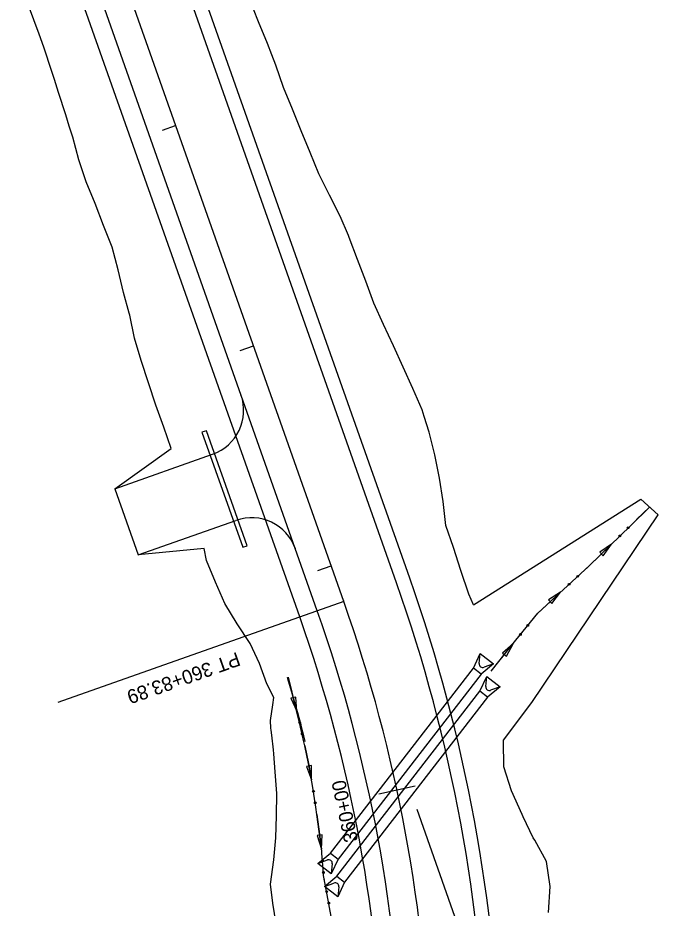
# Model space of a CAD drawing. Extents: x 948761 to 996004, y 1858548 to 1925175.
# Drawn here: x 961167 to 961441.5, y 1906970.6 to 1907351.9 of the extents above; entities that cross this region are included whole.
import ezdxf

# ---------------------------------------------------------------- set-up
doc = ezdxf.new("R2010")
doc.units = 0
for name, color, linetype in [('62', 7, 'Continuous'), ('DRAINAGE STRUCTURES', 7, 'Continuous'), ('R_Drainage', 7, 'Continuous'), ('R_Horz Alg', 7, 'Continuous'), ('R_Horz Alg Annot', 7, 'Continuous'), ('R_Proposed Const Limits', 7, 'Continuous'), ('R_Proposed Road', 7, 'Continuous')]:
    doc.layers.add(name, color=color, linetype=linetype)

msp = doc.modelspace()

# ---------------------------------------------------------------- linework, layer by layer
at = {"layer": '62'}
for p, q in [((961421.48, 1907126.54), (961416.45, 1907123.1)), ((961417.93, 1907121.59), (961421.48, 1907126.54)), ((961416.45, 1907123.1), (961417.93, 1907121.59)), ((961399.62, 1907105.94), (961394.48, 1907102.67)), ((961395.91, 1907101.11), (961399.62, 1907105.94)), ((961394.48, 1907102.67), (961395.91, 1907101.11)), ((961379.34, 1907083.9), (961374.76, 1907079.88)), ((961376.41, 1907078.56), (961379.34, 1907083.9)), ((961374.76, 1907079.88), (961376.41, 1907078.56)), ((961286.16, 1907061.07), (961284.11, 1907060.55)), ((961284.11, 1907060.55), (961286.59, 1907054.99)), ((961286.59, 1907054.99), (961286.16, 1907061.07)), ((961292.92, 1907031.72), (961290.83, 1907031.36)), ((961290.83, 1907031.36), (961292.9, 1907025.63)), ((961292.9, 1907025.63), (961292.92, 1907031.72)), ((961297.44, 1907001.99), (961295.34, 1907001.71)), ((961295.34, 1907001.71), (961297.16, 1906995.9)), ((961297.16, 1906995.9), (961297.44, 1907001.99))]:
    msp.add_line(p, q, dxfattribs=at)
for points in [[(961369.95, 1907072.2), (961378.68, 1907083.08), (961389.86, 1907097), (961400.88, 1907107.09), (961411.9, 1907117.17), (961429.71, 1907134.58), (961437.74, 1907142.42)], [(961432.23, 1907137.05), (961437.74, 1907142.42)], [(961432.21, 1907137.02), (961432.23, 1907137.05)], [(961410.72, 1907116.09), (961411.9, 1907117.17), (961421.48, 1907126.54)], [(961410.69, 1907116.06), (961410.72, 1907116.09)], [(961388.75, 1907095.63), (961389.86, 1907097), (961399.62, 1907105.94)], [(961374.53, 1907077.9), (961378.68, 1907083.08), (961389.86, 1907097), (961390.32, 1907097.42)], [(961388.73, 1907095.6), (961388.75, 1907095.63)], [(961369.95, 1907072.2), (961378.68, 1907083.08), (961379.34, 1907083.9)], [(961290.22, 1907042), (961289.59, 1907044.39), (961288.65, 1907048.21), (961288.42, 1907049.12), (961287.86, 1907051.19), (961287.16, 1907053.73), (961287.13, 1907053.81), (961287.01, 1907054.27), (961285.81, 1907058.5), (961285.28, 1907060.33), (961284.46, 1907063.18), (961283.11, 1907067.85), (961282.61, 1907069.44)], [(961298.07, 1906984.71), (961298.01, 1906985.66), (961297.38, 1906994.06), (961297.38, 1906994.06), (961297.27, 1906995.1), (961296.05, 1907004.48), (961294.76, 1907013.87), (961293.32, 1907023.24), (961291.69, 1907032.59), (961290.02, 1907040.16), (961289.64, 1907041.85), (961288.25, 1907048.1), (961287.77, 1907050.19), (961287.55, 1907051.11), (961286.79, 1907054.21), (961285.25, 1907060.32), (961284.52, 1907063.19), (961282.86, 1907069.52)], [(961282.86, 1907069.52), (961284.52, 1907063.19), (961285.25, 1907060.32), (961286.59, 1907054.99)], [(961289.97, 1907040.38), (961289.98, 1907040.34)], [(961289.98, 1907040.34), (961290.02, 1907040.16), (961291.69, 1907032.59), (961292.9, 1907025.63)], [(961295.18, 1907010.81), (961295.18, 1907010.77)], [(961295.18, 1907010.77), (961296.05, 1907004.48), (961297.16, 1906995.9)], [(961311.79, 1906863.42), (961311.52, 1906872.94), (961311.16, 1906882.44), (961310.67, 1906891.93), (961309.86, 1906901.4), (961308.95, 1906910.85), (961307.92, 1906920.28), (961306.82, 1906929.69), (961305.64, 1906939.07), (961304.35, 1906948.44), (961302.96, 1906957.79), (961301.39, 1906967.1), (961299.69, 1906976.38), (961298.07, 1906984.71)], [(961298.46, 1906982.68), (961298.07, 1906984.71)], [(961298.47, 1906982.64), (961298.46, 1906982.68)]]:
    msp.add_lwpolyline(points, dxfattribs=at)
for centre in [(961428.62, 1907133.56), (961425.03, 1907130.06), (961403.29, 1907109.34), (961406.99, 1907112.73), (961385.58, 1907091.73), (961382.44, 1907087.83), (961287.82, 1907050.14), (961288.92, 1907045.25), (961293.75, 1907020.7), (961294.51, 1907015.74), (961297.65, 1906990.92), (961298.02, 1906985.92), (961299.39, 1906977.75), (961300.3, 1906972.82)]:
    msp.add_circle(centre, 0.375, dxfattribs=at)
at = {"layer": 'DRAINAGE STRUCTURES'}
for p, q in [((961364.8, 1907075.4), (961365.25, 1907079.77)), ((961365.25, 1907079.77), (961370.97, 1907075.34)), ((961370.97, 1907075.34), (961366.86, 1907073.81)), ((961367.57, 1907065.52), (961368.02, 1907069.89)), ((961368.02, 1907069.89), (961373.75, 1907065.46)), ((961373.75, 1907065.46), (961369.63, 1907063.93)), ((961295.63, 1906989.76), (961299.75, 1906991.3)), ((961301.36, 1906985.34), (961295.63, 1906989.76)), ((961301.81, 1906989.71), (961301.36, 1906985.34)), ((961298.41, 1906979.88), (961302.52, 1906981.42)), ((961304.13, 1906975.46), (961298.41, 1906979.88)), ((961304.58, 1906979.83), (961304.13, 1906975.46))]:
    msp.add_line(p, q, dxfattribs=at)
for points in [[(961370.97, 1907075.34), (961365.55, 1907070.91), (961362.32, 1907073.41), (961365.25, 1907079.77)], [(961373.75, 1907065.46), (961368.33, 1907061.03), (961365.1, 1907063.53), (961368.02, 1907069.89)], [(961295.63, 1906989.76), (961301.05, 1906994.19), (961304.28, 1906991.7), (961301.36, 1906985.34)], [(961298.41, 1906979.88), (961303.83, 1906984.31), (961307.06, 1906981.82), (961304.13, 1906975.46)]]:
    msp.add_lwpolyline(points, close=True, dxfattribs=at)
for centre, start, end in [((961366.32, 1907075.24), 174.1358, 290.4227), ((961369.1, 1907065.36), 174.1358, 290.4227), ((961300.29, 1906989.86), 354.1358, 110.4227), ((961303.06, 1906979.98), 354.1358, 110.4227)]:
    msp.add_arc(centre, 1.53, start, end, dxfattribs=at)
at = {"layer": 'R_Drainage'}
for p, q in [((961247.86, 1907175.09), (961245.98, 1907174.42)), ((961245.98, 1907174.42), (961263.51, 1907125.19)), ((961265.4, 1907125.86), (961247.86, 1907175.09)), ((961263.51, 1907125.19), (961265.4, 1907125.86)), ((961301.05, 1906994.19), (961362.32, 1907073.41)), ((961365.55, 1907070.91), (961304.28, 1906991.7)), ((961303.83, 1906984.31), (961365.1, 1907063.53)), ((961368.33, 1907061.03), (961307.06, 1906981.82))]:
    msp.add_line(p, q, dxfattribs=at)
at = {"layer": 'R_Horz Alg'}
msp.add_line((961306.71, 1907102.01), (961185.9, 1907443.82), dxfattribs=at)
msp.add_arc((960689.32, 1906883.81), 654.81, 343.56518, 19.46478, dxfattribs=at)
at = {"layer": 'R_Horz Alg Annot'}
msp.add_line((961377.39, 1906902), (961338.2, 1907012.88), dxfattribs=at)
for points in [[(961229.04, 1907303.76), (961234.69, 1907305.76)], [(961262.36, 1907209.48), (961268.02, 1907211.48)], [(961295.68, 1907115.2), (961301.34, 1907117.19)], [(961306.71, 1907102.01), (961184.14, 1907058.69)], [(961321.7, 1907019.66), (961337.35, 1907023.02)]]:
    msp.add_lwpolyline(points, dxfattribs=at)
at = {"layer": 'R_Proposed Const Limits'}
msp.add_line((961362.37, 1907100.56), (961433.99, 1907145.75), dxfattribs=at)
for points in [[(961208.69, 1907150.21), (961232.72, 1907167.51), (961229.58, 1907176.68), (961226.15, 1907186.08), (961223.05, 1907195.59), (961219.94, 1907205.1), (961217.08, 1907214.69), (961215.01, 1907224.56), (961214.84, 1907225.45), (961212.4, 1907234.25), (961210.1, 1907244.04), (961207.47, 1907253.72), (961203.78, 1907263.02), (961200.16, 1907272.35), (961196.39, 1907281.62), (961193.19, 1907291.09), (961190.61, 1907300.79), (961189.13, 1907305.46), (961187.59, 1907310.33), (961184.54, 1907319.86), (961182.72, 1907325.46), (961181.45, 1907329.37), (961178.4, 1907338.9), (961176.02, 1907345.36), (961174.91, 1907348.27), (961171.42, 1907357.65)], [(961362.34, 1907100.54), (961360.4, 1907105.08), (961356.9, 1907115.29), (961353.75, 1907125.11), (961350.5, 1907134.57), (961349.29, 1907144.75), (961347.71, 1907154.8), (961345.73, 1907164.7), (961343.29, 1907174.45), (961341.21, 1907181.14), (961340.32, 1907184), (961336.33, 1907193.2), (961332.22, 1907202.35), (961328, 1907211.47), (961323.79, 1907220.59), (961319.69, 1907229.74), (961316.22, 1907239.12), (961312.58, 1907248.44), (961309.05, 1907257.8), (961308.73, 1907258.63), (961305.13, 1907267.02), (961300.6, 1907276.03), (961296.07, 1907285.03), (961292.28, 1907294.3), (961288.48, 1907303.56), (961284.7, 1907312.83), (961280.89, 1907322.09), (961277.67, 1907331.56), (961275.89, 1907336.12), (961274.01, 1907340.87), (961270.24, 1907350.15), (961268.07, 1907355.62)], [(961387.33, 1907058.75), (961441.49, 1907139.1), (961433.99, 1907145.75)], [(961273.75, 1907066.67), (961270.62, 1907075.48), (961266.57, 1907083.97), (961261.03, 1907092.34), (961255.74, 1907101.08), (961251.79, 1907110.29), (961247.88, 1907119.51), (961246.86, 1907124.64), (961218.69, 1907121.92)], [(961277.79, 1906963.89), (961276.29, 1906972.83), (961275.4, 1906980.96), (961275.52, 1906981.89), (961276.62, 1906990.29), (961276.62, 1906990.29), (961276.74, 1906991.35), (961277.64, 1907000.82), (961277.94, 1907010.26), (961277.99, 1907019.71), (961277.35, 1907029.05), (961276.74, 1907036.7), (961276.57, 1907038.41), (961275.91, 1907044.72), (961275.66, 1907046.82), (961275.54, 1907047.75), (961275.38, 1907050.95), (961276.38, 1907057.69), (961276.77, 1907060.86), (961273.75, 1907066.67)], [(961375.21, 1907042.54), (961387.33, 1907058.75)], [(961378.68, 1907020.92), (961375.3, 1907031.17), (961375.26, 1907042.16), (961375.21, 1907042.54)], [(961394.48, 1906968.82), (961395.16, 1906979.86), (961393.56, 1906990.62), (961388.58, 1906999.72), (961387.9, 1907000.7), (961383.63, 1907009.7), (961383.63, 1907009.7), (961383.13, 1907010.82), (961378.68, 1907020.92)]]:
    msp.add_lwpolyline(points, dxfattribs=at)
at = {"layer": 'R_Proposed Road'}
for p, q in [((961334.99, 1907112), (961214.19, 1907453.82)), ((961329.33, 1907110), (961208.53, 1907451.82)), ((961295.39, 1907098.01), (961174.59, 1907439.82)), ((961287.85, 1907095.34), (961167.04, 1907437.15)), ((961208.69, 1907150.21), (961250.51, 1907164.99)), ((961208.69, 1907150.21), (961218.69, 1907121.92)), ((961218.69, 1907121.92), (961260.5, 1907136.7))]:
    msp.add_line(p, q, dxfattribs=at)
for centre, radius, start, end in [((961243.84, 1907183.85), 20, 289.4648, 19.4648), ((961267.17, 1907117.85), 20, 19.4648, 109.4648), ((960689.32, 1906883.81), 678.81, 343.56518, 19.46478), ((960689.32, 1906883.81), 684.81, 343.56518, 19.46478), ((960689.32, 1906883.81), 634.81, 343.56518, 19.46478), ((960689.32, 1906883.81), 642.81, 343.56518, 19.46478)]:
    msp.add_arc(centre, radius, start, end, dxfattribs=at)

# ---------------------------------------------------------------- texts
at = {"layer": 'R_Horz Alg'}
msp.add_text('+', height=1, rotation=109.4648, dxfattribs=at).set_placement((961307.18, 1907102.17))
at = {"layer": 'R_Horz Alg Annot'}
for s, rotation, p in [('PT 360+83.89', 199.4648, (961261, 1907080.44)), ('360+00', 102.1244, (961312.96, 1906999.56))]:
    msp.add_text(s, height=6, rotation=rotation, dxfattribs=at).set_placement(p)

doc.saveas('drawing.dxf')
